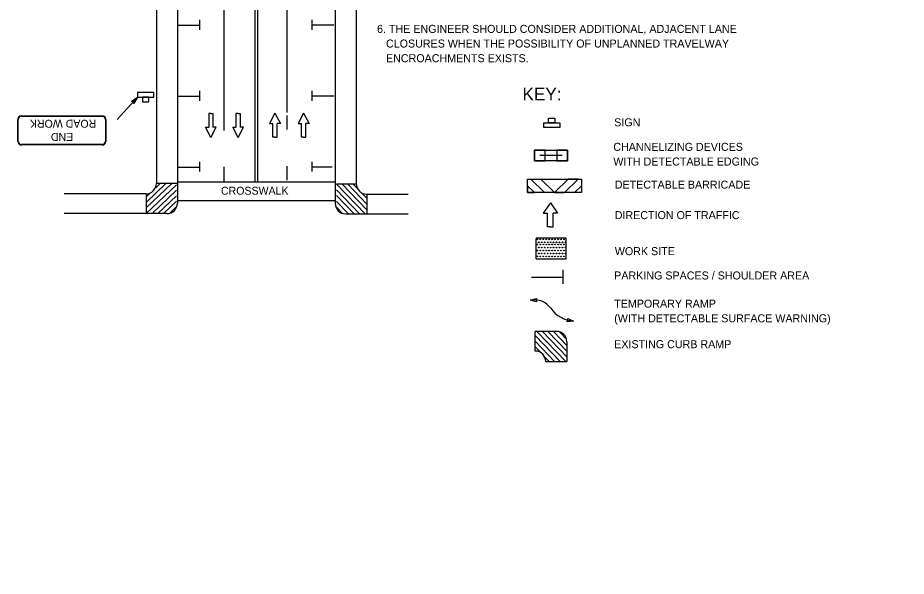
# Model space of a CAD drawing. Extents: x 12.69 to 19.62, y 5.94 to 15.87.
# Drawn here: x 12.96 to 19.62, y 5.94 to 10.13 of the extents above; entities that cross this region are included whole.
import ezdxf

# ---------------------------------------------------------------- set-up
doc = ezdxf.new("R2010")
doc.units = 0
for name, color, linetype in [('DETL-LINE', 7, 'Continuous'), ('ENGLISH', 7, 'Continuous'), ('TTLB-TEXT', 7, 'Continuous'), ('V7_LEVEL_1', 7, 'Continuous'), ('V7_LEVEL_10', 7, 'Continuous'), ('V7_LEVEL_13', 7, 'Continuous')]:
    doc.layers.add(name, color=color, linetype=linetype)

# ---------------------------------------------------------------- blocks, each defined once
blk = doc.blocks.new('DIR2')
for p, q in [((0, 0.012), (-0.342, -0.477)), ((0, 0.012), (0.342, -0.477)), ((-0.342, -0.477), (-0.132, -0.477)), ((-0.132, -1.133), (-0.132, -0.477)), ((0.342, -0.477), (0.132, -0.477)), ((0.132, -1.133), (0.132, -0.477)), ((-0.011, -1.133), (-0.132, -1.133)), ((-0.011, -1.133), (0.011, -1.133)), ((0.011, -1.133), (0.132, -1.133))]:
    blk.add_line(p, q)

msp = doc.modelspace()

# ---------------------------------------------------------------- linework, layer by layer
at = {"layer": 'DETL-LINE'}
for p, q in [((13.9226, 8.7003), (14.1165, 8.8855)), ((13.9226, 8.7418), (14.073, 8.8855)), ((13.9226, 8.6589), (14.1489, 8.875)), ((13.994, 8.8515), (14.0296, 8.8855)), ((14.0017, 8.8855), (14.154, 8.8855)), ((15.498, 8.8802), (15.3505, 8.8802)), ((15.3505, 8.8802), (15.5643, 8.6563)), ((15.392, 8.8802), (15.5771, 8.6863)), ((15.4334, 8.8802), (15.5771, 8.7298)), ((15.4749, 8.8802), (15.5042, 8.8495)), ((13.9226, 8.7833), (13.9533, 8.8126)), ((13.9226, 8.8064), (13.9226, 8.6589)), ((13.9661, 8.6589), (14.1489, 8.8335)), ((15.3505, 8.8367), (15.5228, 8.6563)), ((15.5431, 8.8088), (15.5771, 8.7732)), ((15.5771, 8.8011), (15.5771, 8.6563)), ((14.0095, 8.6589), (14.1489, 8.792)), ((14.0529, 8.6589), (14.1489, 8.7505)), ((15.3505, 8.7933), (15.4813, 8.6563)), ((15.3505, 8.7499), (15.4398, 8.6563)), ((14.0985, 8.6609), (14.1453, 8.7056)), ((15.3525, 8.7043), (15.3947, 8.6601)), ((16.8396, 7.6271), (16.8396, 7.7747)), ((16.9977, 7.7747), (16.8396, 7.7747)), ((17.0265, 7.5485), (16.8414, 7.7423)), ((17.068, 7.5485), (16.8519, 7.7748)), ((17.0768, 7.5828), (16.8934, 7.7748)), ((17.0768, 7.6262), (16.9349, 7.7748)), ((17.0768, 7.6696), (16.9764, 7.7748)), ((17.0742, 7.7158), (17.0213, 7.7711)), ((16.9851, 7.5485), (16.8414, 7.6989)), ((17.0768, 7.6957), (17.0768, 7.5481)), ((16.8754, 7.6199), (16.8414, 7.6555)), ((16.9436, 7.5485), (16.9143, 7.5792)), ((16.9186, 7.5481), (17.0768, 7.5481))]:
    msp.add_line(p, q, dxfattribs=at)
at = {"layer": 'TTLB-TEXT'}
msp.add_line((19.6215, 5.9375), (19.6215, 5.9375), dxfattribs=at)
at = {"layer": 'V7_LEVEL_1'}
for p, q in [((14.5059, 14.9247), (14.5059, 9.3607)), ((14.9772, 14.9247), (14.9772, 9.4166)), ((14.1569, 13.5569), (14.1569, 10.0715)), ((15.3398, 13.5589), (15.3398, 8.7364)), ((13.9987, 13.4095), (13.9987, 10.0715)), ((14.7362, 13.3953), (14.7362, 10.0715)), ((14.7568, 13.3953), (14.7568, 10.0715)), ((15.498, 13.4114), (15.498, 8.8802)), ((13.9987, 10.0715), (13.9987, 8.8847)), ((14.1569, 10.0715), (14.3214, 10.0715)), ((14.1569, 10.0715), (14.3214, 10.0715)), ((14.1569, 10.0715), (14.1569, 8.7371)), ((14.3214, 10.1111), (14.3214, 10.0715)), ((14.3214, 10.0715), (14.3214, 10.037)), ((14.7362, 10.0715), (14.7362, 8.8955)), ((14.7568, 10.0715), (14.7568, 8.8955)), ((15.1647, 10.1111), (15.1647, 10.0715)), ((15.3293, 10.0715), (15.1647, 10.0715)), ((15.1647, 10.0715), (15.1647, 10.0369)), ((14.1569, 9.5395), (14.3214, 9.5395)), ((14.3214, 9.5792), (14.3214, 9.5049)), ((15.1647, 9.5792), (15.1647, 9.5049)), ((15.3293, 9.5395), (15.1647, 9.5395)), ((12.9595, 9.1997), (12.9595, 9.3653)), ((12.9627, 9.1997), (12.9627, 9.3653)), ((12.9864, 9.3922), (13.5938, 9.3922)), ((12.9864, 9.389), (13.5938, 9.389)), ((13.6175, 9.3653), (13.6175, 9.1997)), ((13.6207, 9.3653), (13.6207, 9.1997)), ((13.5938, 9.176), (12.9864, 9.176)), ((13.5938, 9.1729), (12.9864, 9.1729)), ((14.1569, 9.0075), (14.3214, 9.0075)), ((14.3214, 9.0471), (14.3214, 8.9729)), ((15.1647, 9.0471), (15.1647, 8.9729)), ((15.3173, 9.0075), (15.1647, 9.0075)), ((14.1569, 8.8955), (15.3398, 8.8955)), ((13.9197, 8.8056), (13.3076, 8.8056)), ((15.577, 8.8039), (15.8859, 8.8039)), ((15.3398, 8.7537), (14.1569, 8.7537)), ((14.0779, 8.6581), (13.3076, 8.6581)), ((15.4189, 8.6563), (15.8859, 8.6563)), ((17.0728, 8.4727), (16.8471, 8.4727)), ((17.0728, 8.4727), (16.8471, 8.4727)), ((17.0728, 8.4727), (16.8471, 8.4727)), ((17.0728, 8.4727), (16.8471, 8.4727)), ((16.8472, 8.318), (16.8472, 8.4726)), ((16.8472, 8.3181), (16.8472, 8.4726)), ((16.8548, 8.4648), (16.8548, 8.4648)), ((16.8555, 8.4648), (16.8555, 8.4648)), ((16.8775, 8.4648), (16.8775, 8.4648)), ((16.8775, 8.4648), (16.8775, 8.4648)), ((16.8995, 8.4648), (16.8995, 8.4648)), ((16.9002, 8.4648), (16.9002, 8.4648)), ((16.9216, 8.4648), (16.9216, 8.4648)), ((16.9223, 8.4648), (16.9223, 8.4648)), ((16.9436, 8.4648), (16.9436, 8.4648)), ((16.9443, 8.4648), (16.9443, 8.4648)), ((16.9663, 8.4648), (16.9663, 8.4648)), ((16.9663, 8.4648), (16.9663, 8.4648)), ((16.9884, 8.4648), (16.9884, 8.4648)), ((16.9884, 8.4648), (16.9884, 8.4648)), ((17.0104, 8.4648), (17.0104, 8.4648)), ((17.0111, 8.4648), (17.0111, 8.4648)), ((17.0324, 8.4648), (17.0324, 8.4648)), ((17.0331, 8.4648), (17.0331, 8.4648)), ((17.0552, 8.4648), (17.0552, 8.4648)), ((17.0552, 8.4648), (17.0552, 8.4648)), ((17.0728, 8.3181), (17.0728, 8.4727)), ((17.0728, 8.3181), (17.0728, 8.4727)), ((17.0728, 8.3181), (17.0728, 8.4727)), ((17.0728, 8.3181), (17.0728, 8.4727)), ((16.8548, 8.4259), (16.8548, 8.4259)), ((16.8555, 8.4259), (16.8555, 8.4259)), ((16.8661, 8.4427), (16.8661, 8.4427)), ((16.8661, 8.4427), (16.8661, 8.4427)), ((16.8661, 8.4031), (16.8661, 8.4031)), ((16.8775, 8.4259), (16.8775, 8.4259)), ((16.8775, 8.4259), (16.8775, 8.4259)), ((16.8882, 8.4427), (16.8882, 8.4427)), ((16.8882, 8.4427), (16.8882, 8.4427)), ((16.8882, 8.4031), (16.8882, 8.4031)), ((16.8995, 8.4259), (16.8995, 8.4259)), ((16.9002, 8.4259), (16.9002, 8.4259)), ((16.9109, 8.4427), (16.9109, 8.4427)), ((16.9109, 8.4427), (16.9109, 8.4427)), ((16.9109, 8.4031), (16.9109, 8.4031)), ((16.9216, 8.4259), (16.9216, 8.4259)), ((16.9223, 8.4259), (16.9223, 8.4259)), ((16.9329, 8.4427), (16.9329, 8.4427)), ((16.9329, 8.4427), (16.9329, 8.4427)), ((16.9329, 8.4031), (16.9329, 8.4031)), ((16.9436, 8.4259), (16.9436, 8.4259)), ((16.9443, 8.4259), (16.9443, 8.4259)), ((16.955, 8.4427), (16.955, 8.4427)), ((16.955, 8.4427), (16.955, 8.4427)), ((16.955, 8.4031), (16.955, 8.4031)), ((16.9663, 8.4259), (16.9663, 8.4259)), ((16.9663, 8.4259), (16.9663, 8.4259)), ((16.977, 8.4427), (16.977, 8.4427)), ((16.977, 8.4427), (16.977, 8.4427)), ((16.977, 8.4031), (16.977, 8.4031)), ((16.9884, 8.4259), (16.9884, 8.4259)), ((16.9884, 8.4259), (16.9884, 8.4259)), ((16.999, 8.4427), (16.999, 8.4427)), ((16.999, 8.4427), (16.999, 8.4427)), ((16.999, 8.4031), (16.999, 8.4031)), ((17.0104, 8.4259), (17.0104, 8.4259)), ((17.0111, 8.4259), (17.0111, 8.4259)), ((17.0218, 8.4427), (17.0218, 8.4427)), ((17.0218, 8.4427), (17.0218, 8.4427)), ((17.0218, 8.4031), (17.0218, 8.4031)), ((17.0324, 8.4259), (17.0324, 8.4259)), ((17.0331, 8.4259), (17.0331, 8.4259)), ((17.0438, 8.4427), (17.0438, 8.4427)), ((17.0438, 8.4427), (17.0438, 8.4427)), ((17.0438, 8.4031), (17.0438, 8.4031)), ((17.0552, 8.4259), (17.0552, 8.4259)), ((17.0552, 8.4259), (17.0552, 8.4259)), ((17.0658, 8.4427), (17.0658, 8.4427)), ((17.0658, 8.4427), (17.0658, 8.4427)), ((17.0658, 8.4031), (17.0658, 8.4031)), ((16.8548, 8.3811), (16.8548, 8.3811)), ((16.8548, 8.3374), (16.8548, 8.3374)), ((16.8555, 8.3811), (16.8555, 8.3811)), ((16.8555, 8.3374), (16.8555, 8.3374)), ((16.8661, 8.3591), (16.8661, 8.3591)), ((16.8661, 8.3591), (16.8661, 8.3591)), ((16.8775, 8.3811), (16.8775, 8.3811)), ((16.8775, 8.3811), (16.8775, 8.3811)), ((16.8775, 8.3374), (16.8775, 8.3374)), ((16.8775, 8.3374), (16.8775, 8.3374)), ((16.8882, 8.3591), (16.8882, 8.3591)), ((16.8882, 8.3591), (16.8882, 8.3591)), ((16.8995, 8.3811), (16.8995, 8.3811)), ((16.8995, 8.3374), (16.8995, 8.3374)), ((16.9002, 8.3811), (16.9002, 8.3811)), ((16.9002, 8.3374), (16.9002, 8.3374)), ((16.9109, 8.3591), (16.9109, 8.3591)), ((16.9109, 8.3591), (16.9109, 8.3591)), ((16.9216, 8.3811), (16.9216, 8.3811)), ((16.9216, 8.3374), (16.9216, 8.3374)), ((16.9223, 8.3811), (16.9223, 8.3811)), ((16.9223, 8.3374), (16.9223, 8.3374)), ((16.9329, 8.3591), (16.9329, 8.3591)), ((16.9329, 8.3591), (16.9329, 8.3591)), ((16.9436, 8.3811), (16.9436, 8.3811)), ((16.9436, 8.3374), (16.9436, 8.3374)), ((16.9443, 8.3811), (16.9443, 8.3811)), ((16.9443, 8.3374), (16.9443, 8.3374)), ((16.955, 8.3591), (16.955, 8.3591)), ((16.955, 8.3591), (16.955, 8.3591)), ((16.9663, 8.3811), (16.9663, 8.3811)), ((16.9663, 8.3811), (16.9663, 8.3811)), ((16.9663, 8.3374), (16.9663, 8.3374)), ((16.9663, 8.3374), (16.9663, 8.3374)), ((16.977, 8.3591), (16.977, 8.3591)), ((16.977, 8.3591), (16.977, 8.3591)), ((16.9884, 8.3811), (16.9884, 8.3811)), ((16.9884, 8.3811), (16.9884, 8.3811)), ((16.9884, 8.3374), (16.9884, 8.3374)), ((16.9884, 8.3374), (16.9884, 8.3374)), ((16.999, 8.3591), (16.999, 8.3591)), ((16.999, 8.3591), (16.999, 8.3591)), ((17.0104, 8.3811), (17.0104, 8.3811)), ((17.0104, 8.3374), (17.0104, 8.3374)), ((17.0111, 8.3811), (17.0111, 8.3811)), ((17.0111, 8.3374), (17.0111, 8.3374)), ((17.0218, 8.3591), (17.0218, 8.3591)), ((17.0218, 8.3591), (17.0218, 8.3591)), ((17.0324, 8.3811), (17.0324, 8.3811)), ((17.0324, 8.3374), (17.0324, 8.3374)), ((17.0331, 8.3811), (17.0331, 8.3811)), ((17.0331, 8.3374), (17.0331, 8.3374)), ((17.0438, 8.3591), (17.0438, 8.3591)), ((17.0438, 8.3591), (17.0438, 8.3591)), ((17.0552, 8.3811), (17.0552, 8.3811)), ((17.0552, 8.3811), (17.0552, 8.3811)), ((17.0552, 8.3374), (17.0552, 8.3374)), ((17.0552, 8.3374), (17.0552, 8.3374)), ((17.0658, 8.3591), (17.0658, 8.3591)), ((17.0658, 8.3591), (17.0658, 8.3591)), ((16.8472, 8.318), (17.0728, 8.318)), ((17.0468, 8.2375), (17.0468, 8.1312)), ((16.8113, 8.1807), (17.0468, 8.1807))]:
    msp.add_line(p, q, dxfattribs=at)
for points in [[(14.5059, 9.7869), (14.5059, 9.6803)], [(14.9772, 9.7869), (14.9772, 9.6803)], [(14.9772, 9.3951), (14.9772, 9.2885)], [(14.5059, 9.3893), (14.5059, 9.2827)], [(14.5059, 9.0091), (14.5059, 8.9025)], [(14.9772, 9.0149), (14.9772, 8.9083)]]:
    msp.add_lwpolyline(points, dxfattribs=at)
for points in [[(13.9795, 9.5321), (13.9795, 9.567), (13.8583, 9.567), (13.8583, 9.5321)], [(13.8955, 9.496), (13.9422, 9.496), (13.9422, 9.5321), (13.8955, 9.5321)], [(17.0241, 9.3382), (17.0241, 9.3034), (16.9029, 9.3034), (16.9029, 9.3382)], [(16.9401, 9.3743), (16.9868, 9.3743), (16.9868, 9.3382), (16.9401, 9.3382)], [(16.8344, 9.0542), (16.914, 9.0542), (16.914, 9.1338), (16.8344, 9.1338)], [(17.0011, 9.0542), (17.0807, 9.0542), (17.0807, 9.1338), (17.0011, 9.1338)], [(16.7823, 8.9172), (17.1867, 8.9172), (17.1867, 8.8155), (16.7823, 8.8155)]]:
    msp.add_lwpolyline(points, close=True, dxfattribs=at)
for centre in [(16.8554, 8.4647), (16.8775, 8.4647), (16.9002, 8.4647), (16.9223, 8.4647), (16.9443, 8.4647), (16.9663, 8.4647), (16.9884, 8.4647), (17.0111, 8.4647), (17.0331, 8.4647), (17.0552, 8.4647), (16.8554, 8.4258), (16.8661, 8.4426), (16.8661, 8.4031), (16.8775, 8.4258), (16.8881, 8.4426), (16.8881, 8.4031), (16.9002, 8.4258), (16.9109, 8.4426), (16.9109, 8.4031), (16.9223, 8.4258), (16.9329, 8.4426), (16.9329, 8.4031), (16.9443, 8.4258), (16.9549, 8.4426), (16.9549, 8.4031), (16.9663, 8.4258), (16.977, 8.4426), (16.977, 8.4031), (16.9884, 8.4258), (16.999, 8.4426), (16.999, 8.4031), (17.0111, 8.4258), (17.0218, 8.4426), (17.0218, 8.4031), (17.0331, 8.4258), (17.0438, 8.4426), (17.0438, 8.4031), (17.0552, 8.4258), (17.0658, 8.4426), (17.0658, 8.4031), (16.8554, 8.3811), (16.8554, 8.3373), (16.8661, 8.359), (16.8775, 8.3811), (16.8775, 8.3373), (16.8881, 8.359), (16.9002, 8.3811), (16.9002, 8.3373), (16.9109, 8.359), (16.9223, 8.3811), (16.9223, 8.3373), (16.9329, 8.359), (16.9443, 8.3811), (16.9443, 8.3373), (16.9549, 8.359), (16.9663, 8.3811), (16.9663, 8.3373), (16.977, 8.359), (16.9884, 8.3811), (16.9884, 8.3373), (16.999, 8.359), (17.0111, 8.3811), (17.0111, 8.3373), (17.0218, 8.359), (17.0331, 8.3811), (17.0331, 8.3373), (17.0438, 8.359), (17.0552, 8.3811), (17.0552, 8.3373), (17.0658, 8.359)]:
    msp.add_circle(centre, 0.00259, dxfattribs=at)
for centre, radius, start, end in [((12.9864, 9.3653), 0.0269, 90, 180), ((12.9864, 9.3653), 0.0237, 90, 180), ((13.5938, 9.3653), 0.0269, 0, 90), ((13.5938, 9.3653), 0.0237, 0, 90), ((12.9864, 9.1997), 0.0269, 180, 270), ((12.9864, 9.1997), 0.0237, 180, 270), ((13.5938, 9.1997), 0.0237, 270, 0), ((13.5938, 9.1997), 0.0269, 270, 0), ((13.9196, 8.8846), 0.0791, 270, 0), ((15.577, 8.8829), 0.0791, 180, 270), ((14.0778, 8.7371), 0.0791, 270, 0), ((15.4189, 8.7354), 0.0791, 180, 270), ((16.9977, 7.6957), 0.0791, 0, 90), ((16.8396, 7.5481), 0.0791, 0, 90)]:
    msp.add_arc(centre, radius, start, end, dxfattribs=at)
at = {"layer": 'V7_LEVEL_10'}
msp.add_line((13.8583, 9.5321), (13.7056, 9.3646), dxfattribs=at)
for points in [[(13.8583, 9.5321), (13.8305, 9.4838), (13.8111, 9.5024)], [(16.8033, 8.0082), (16.8483, 8.0209), (16.8483, 7.9956)], [(17.1268, 7.8514), (17.0803, 7.8466), (17.0847, 7.8715)]]:
    msp.add_lwpolyline(points, close=True, dxfattribs=at)
at = {"layer": 'V7_LEVEL_13'}
for p, q in [((17.0409, 9.094), (16.8742, 9.094)), ((15.3173, 9.0075), (15.3039, 9.0075))]:
    msp.add_line(p, q, dxfattribs=at)
for points in [[(16.8344, 9.1338), (16.8344, 9.0542)], [(16.8344, 9.1338), (17.0807, 9.1338), (17.0807, 9.0542), (16.8344, 9.0542)], [(16.7823, 8.8664), (16.7823, 8.8155), (16.8338, 8.8155)], [(16.8074, 8.9172), (16.8828, 8.9172), (16.9845, 8.8155), (16.908, 8.8166)], [(17.0862, 8.9172), (16.9845, 8.8155), (17.0598, 8.8155), (17.1616, 8.9172)], [(17.1867, 8.867), (17.1867, 8.8155), (17.1352, 8.8155)]]:
    msp.add_lwpolyline(points, close=True, dxfattribs=at)
for centre, radius, start, end in [((16.8324, 7.859), 0.1521, 35.61712, 101.01807), ((17.1445, 8.0826), 0.2319, 215.61712, 265.61739)]:
    msp.add_arc(centre, radius, start, end, dxfattribs=at)

# ---------------------------------------------------------------- block references
at = {"layer": 'V7_LEVEL_1', "xscale": 0.1185904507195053, "yscale": 0.1581206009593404, "rotation": 180}
for p in [(14.4071, 9.2303), (14.6115, 9.2303)]:
    msp.add_blockref('DIR2', p, dxfattribs=at)
at = {"layer": 'V7_LEVEL_1', "yscale": 0.1581206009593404}
for p, xscale in [((14.888, 9.4105), 0.1185904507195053), ((15.1028, 9.4105), 0.1185904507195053), ((16.9536, 8.7376), 0.1581206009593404)]:
    msp.add_blockref('DIR2', p, dxfattribs=dict(at, xscale=xscale))

# ---------------------------------------------------------------- texts
at = {"layer": 'ENGLISH'}
msp.add_text('KEY:', height=0.09595, dxfattribs=at).set_placement((16.7441, 9.507))
at = {"layer": 'V7_LEVEL_1'}
for s, rotation, p in [('ROAD WORK', 180, (13.5482, 9.362)), ('END', 180, (13.3753, 9.2632)), ('CROSSWALK', 360, (14.4831, 8.8001))]:
    msp.add_text(s, height=0.0593, rotation=rotation, dxfattribs=at).set_placement(p)
at = {"layer": 'V7_LEVEL_13'}
for s, p in [('6. THE ENGINEER SHOULD CONSIDER ADDITIONAL, ADJACENT LANE', (15.6537, 10.014)), ('   CLOSURES WHEN THE POSSIBILITY OF UNPLANNED TRAVELWAY', (15.6537, 9.904)), ('   ENCROACHMENTS EXISTS.', (15.6537, 9.794)), ('SIGN', (17.4319, 9.3128)), ('CHANNELIZING DEVICES', (17.4251, 9.1289)), ('WITH DETECTABLE EDGING', (17.4251, 9.0189)), ('DETECTABLE BARRICADE', (17.4358, 8.8454)), ('DIRECTION OF TRAFFIC', (17.4358, 8.6168)), ('WORK SITE', (17.4363, 8.3464)), ('PARKING SPACES / SHOULDER AREA', (17.4319, 8.164)), ('TEMPORARY RAMP', (17.4319, 7.9525)), ('(WITH DETECTABLE SURFACE WARNING)', (17.4319, 7.8425)), ('EXISTING CURB RAMP', (17.4319, 7.6486))]:
    msp.add_text(s, height=0.06, dxfattribs=at).set_placement(p)

doc.saveas('drawing.dxf')
